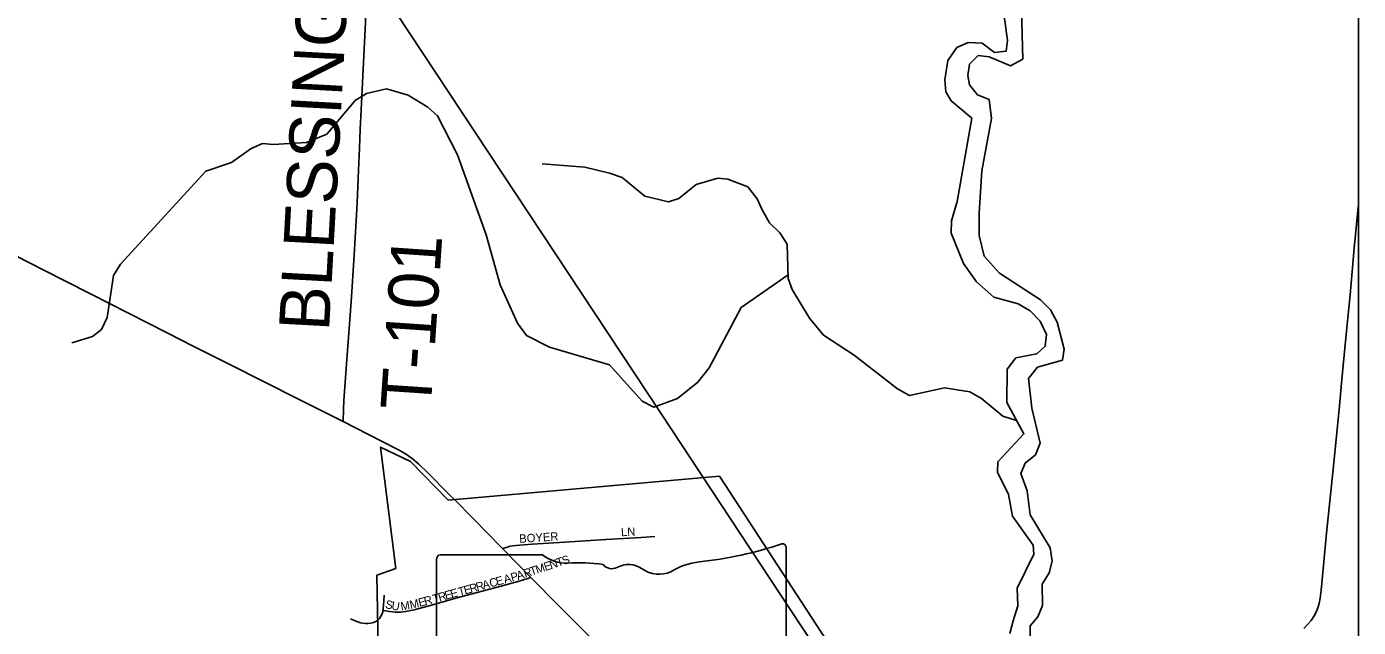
# Model space of a CAD drawing. Extents: x -49 to -8.2, y 9.4 to 23.5.
# Drawn here: x -40.243 to -39.49, y 18.85 to 19.19 of the extents above; entities that cross this region are included whole.
import ezdxf

# ---------------------------------------------------------------- set-up
doc = ezdxf.new("R2010")
doc.units = 0
for name, color, linetype in [('GM_X_Adjacent_County', 7, 'Continuous'), ('GM_X_City_Street', 7, 'Continuous'), ('GM_X_City_Street_Text', 7, 'Continuous'), ('GM_X_Corporation', 7, 'Continuous'), ('GM_X_Minor_River', 7, 'Continuous'), ('GM_X_Rail_Line', 7, 'Continuous'), ('GM_X_State_Route', 7, 'Continuous'), ('GM_X_State_Shield', 7, 'Continuous'), ('GM_X_Township_Road', 7, 'Continuous'), ('GM_X_Township_Road_Text', 7, 'Continuous')]:
    doc.layers.add(name, color=color, linetype=linetype)

msp = doc.modelspace()

# ---------------------------------------------------------------- linework, layer by layer
at = {"layer": 'GM_X_Adjacent_County'}
msp.add_lwpolyline([(-39.48954, 20.58796), (-39.48954, 17.08606), (-39.79885, 17.10416)], dxfattribs=at)
at = {"layer": 'GM_X_City_Street'}
for points in [[(-39.97381, 18.89488), (-39.97082, 18.89572), (-39.96933, 18.89614), (-39.9681, 18.89638), (-39.96627, 18.89659), (-39.95702, 18.89729), (-39.93848, 18.8984), (-39.91532, 18.89992), (-39.89524, 18.90118), (-39.88753, 18.90173)], [(-40.04134, 18.8599), (-40.03753, 18.85924), (-40.03606, 18.85906), (-40.03447, 18.85898), (-40.03133, 18.85892), (-40.02833, 18.85929), (-40.02372, 18.86022), (-40.01605, 18.8623), (-39.998, 18.86728), (-39.9752, 18.87347), (-39.96297, 18.87675), (-39.95767, 18.87857)], [(-40.04134, 18.8599), (-40.04117, 18.86082), (-40.04077, 18.86538), (-40.04065, 18.86844)], [(-40.05981, 18.85512), (-40.05699, 18.85391), (-40.05558, 18.85339), (-40.05413, 18.85295), (-40.05268, 18.85262), (-40.05122, 18.85247), (-40.04973, 18.85251), (-40.04825, 18.85269), (-40.0468, 18.85302), (-40.04544, 18.85353), (-40.04428, 18.85431), (-40.04332, 18.8554), (-40.0425, 18.85664), (-40.04185, 18.85795), (-40.04151, 18.85906), (-40.04134, 18.8599)]]:
    msp.add_lwpolyline(points, dxfattribs=at)
at = {"layer": 'GM_X_Corporation'}
msp.add_lwpolyline([(-39.7113, 18.72151), (-39.85087, 18.93577), (-40.00444, 18.92212), (-40.02576, 18.94403), (-40.04272, 18.95226), (-40.03415, 18.88366), (-40.04482, 18.87976), (-40.04155, 18.71218)], dxfattribs=at)
at = {"layer": 'GM_X_Minor_River'}
for points in [[(-39.67524, 18.83978), (-39.67518, 18.85116), (-39.6708, 18.85626), (-39.6683, 18.8627), (-39.66843, 18.87465), (-39.66442, 18.88108), (-39.66268, 18.88771), (-39.66397, 18.8953), (-39.67523, 18.91395), (-39.67686, 18.92743), (-39.68041, 18.93731), (-39.6781, 18.94318), (-39.67221, 18.94789), (-39.66953, 18.95451), (-39.67434, 18.97427), (-39.67615, 18.99097), (-39.67101, 18.99739), (-39.65698, 19.00131), (-39.656, 19.00756), (-39.65989, 19.02294), (-39.66364, 19.02979), (-39.66929, 19.03551), (-39.69249, 19.05061), (-39.70115, 19.06014), (-39.70412, 19.07192), (-39.70405, 19.08463), (-39.7026, 19.10833), (-39.69715, 19.13809), (-39.69842, 19.14872), (-39.70503, 19.15141), (-39.70954, 19.15712), (-39.71046, 19.16225), (-39.70948, 19.16869), (-39.70472, 19.1736), (-39.69848, 19.17281), (-39.68639, 19.16782), (-39.67937, 19.17158), (-39.68017, 19.19966)], [(-39.68984, 19.1961), (-39.68802, 19.18206), (-39.68881, 19.17599), (-39.69544, 19.17526), (-39.70241, 19.18061), (-39.71036, 19.18103), (-39.71662, 19.17821), (-39.72177, 19.17084), (-39.72353, 19.15985), (-39.723, 19.15301), (-39.71981, 19.14807), (-39.70812, 19.13814), (-39.71651, 19.09114), (-39.71979, 19.08015), (-39.71982, 19.07313)], [(-39.81217, 19.04952), (-39.83873, 19.03123), (-39.85689, 18.99699), (-39.86318, 18.98886), (-39.87477, 18.97962), (-39.88805, 18.97476), (-39.89465, 18.97821), (-39.91328, 18.99878), (-39.94712, 19.00863), (-39.96014, 19.01533), (-39.96522, 19.02237), (-39.97513, 19.04405), (-39.98294, 19.07216), (-39.99917, 19.11739), (-40.01041, 19.13945), (-40.01606, 19.14441), (-40.02701, 19.1511), (-40.03929, 19.15476), (-40.05066, 19.15216), (-40.05712, 19.14821), (-40.07312, 19.12913), (-40.08469, 19.12444), (-40.10343, 19.12321), (-40.10949, 19.12381), (-40.11594, 19.12099), (-40.12696, 19.11308), (-40.14156, 19.10822), (-40.18991, 19.05572), (-40.19373, 19.04929), (-40.19745, 19.02541), (-40.20052, 19.01878), (-40.20565, 19.01482), (-40.21741, 19.01109)], [(-39.68287, 18.96721), (-39.69065, 18.96979), (-39.70271, 18.97972), (-39.70931, 18.98355), (-39.72369, 18.9857), (-39.7434, 18.98144), (-39.75019, 18.98508), (-39.7747, 19.00417), (-39.79205, 19.01545), (-39.80014, 19.02516), (-39.8099, 19.04133), (-39.81214, 19.0476), (-39.81261, 19.06695), (-39.81674, 19.07342), (-39.82276, 19.07896), (-39.82689, 19.08638), (-39.8297, 19.09265), (-39.83496, 19.09931), (-39.8463, 19.10373), (-39.85197, 19.10433), (-39.8641, 19.1006), (-39.87399, 19.09268), (-39.87987, 19.09081), (-39.89329, 19.0941), (-39.90611, 19.1046), (-39.91328, 19.1071), (-39.92709, 19.11039), (-39.9513, 19.11241)], [(-39.71982, 19.07313), (-39.71291, 19.05603), (-39.70558, 19.04556), (-39.69578, 19.03697), (-39.68198, 19.0333), (-39.67519, 19.02928), (-39.66954, 19.02337), (-39.66599, 19.01596), (-39.66678, 19.00932), (-39.67153, 19.00498), (-39.68328, 19.00276), (-39.68823, 18.99634), (-39.68833, 18.97737), (-39.67877, 18.95968), (-39.69343, 18.94382), (-39.69365, 18.93813), (-39.68747, 18.92539), (-39.68526, 18.91324), (-39.67342, 18.89668), (-39.67307, 18.89174), (-39.68264, 18.87244), (-39.68212, 18.86239), (-39.68482, 18.85406), (-39.68675, 18.84686)]]:
    msp.add_lwpolyline(points, dxfattribs=at)
at = {"layer": 'GM_X_Rail_Line'}
msp.add_lwpolyline([(-39.62432, 18.5853), (-39.64583, 18.61097), (-39.65324, 18.62101), (-39.67003, 18.64579), (-39.7037, 18.69732), (-39.73465, 18.7448), (-39.81071, 18.86022), (-39.88413, 18.97135), (-40.04901, 19.22076)], dxfattribs=at)
at = {"layer": 'GM_X_State_Route'}
for points in [[(-39.52045, 18.84966), (-39.51828, 18.85184), (-39.51628, 18.85419), (-39.51454, 18.85673), (-39.51379, 18.85806), (-39.51259, 18.86086), (-39.51175, 18.8638), (-39.51112, 18.86681), (-39.51051, 18.87139), (-39.50731, 18.9054), (-39.504, 18.93785), (-39.50048, 18.97339), (-39.4988, 18.99039), (-39.4968, 19.01204), (-39.49423, 19.03831), (-39.49187, 19.06461), (-39.48966, 19.0878), (-39.48954, 19.08905)], [(-40.04214, 18.95566), (-40.0639, 18.96676), (-40.08719, 18.97838), (-40.11075, 18.99033), (-40.12603, 18.99798), (-40.13853, 19.00424), (-40.14828, 19.00906), (-40.16353, 19.01678), (-40.18567, 19.0281), (-40.20639, 19.03877), (-40.22164, 19.04647), (-40.24246, 19.05694), (-40.26727, 19.06986)], [(-40.00074, 18.92245), (-40.00384, 18.9255), (-40.01574, 18.93757), (-40.02132, 18.94284), (-40.02486, 18.94576), (-40.02862, 18.94837), (-40.03258, 18.95069), (-40.04214, 18.95566)], [(-39.78571, 18.6853), (-39.79173, 18.6926), (-39.81463, 18.71994), (-39.83438, 18.74385), (-39.8483, 18.7605), (-39.87303, 18.79035), (-39.88311, 18.80211), (-39.88936, 18.80898), (-39.9023, 18.82234), (-39.92507, 18.84561), (-39.94142, 18.86215), (-39.95767, 18.87857), (-39.97381, 18.89488), (-39.97414, 18.89522), (-39.99039, 18.91185), (-40.00074, 18.92245)]]:
    msp.add_lwpolyline(points, dxfattribs=at)
at = {"layer": 'GM_X_State_Shield'}
for p, q in [((-40.01102, 18.88876), (-40.01102, 18.73867)), ((-39.95116, 18.89135), (-40.00907, 18.89135)), ((-39.81327, 18.81655), (-39.81327, 18.89507))]:
    msp.add_line(p, q, dxfattribs=at)
for centre, radius, start, end in [((-39.88371, 19.09597), 0.20971, 275.84447, 288.90645), ((-39.81546, 18.89539), 0.0022, 351.86209, 97.738), ((-40.00875, 18.88908), 0.00229, 98.1301, 188.1301), ((-39.93737, 18.90877), 0.02222, 231.61951, 271.11188), ((-39.93, 18.80708), 0.07977, 80.48669, 94.98827), ((-39.91189, 18.88986), 0.00641, 219.79206, 297.10237), ((-39.90248, 18.87251), 0.01333, 54.46668, 119.14113), ((-39.88528, 18.89631), 0.01603, 233.85621, 294.82819), ((-39.85696, 18.84551), 0.04219, 97.34618, 120.76885)]:
    msp.add_arc(centre, radius, start, end, dxfattribs=at)
at = {"layer": 'GM_X_Township_Road'}
msp.add_lwpolyline([(-40.0639, 18.96676), (-40.06368, 18.9739), (-40.06348, 18.97855), (-40.06186, 19.0018), (-40.05939, 19.03433), (-40.05759, 19.06066), (-40.05604, 19.09013), (-40.05519, 19.10876), (-40.05465, 19.12117), (-40.0542, 19.13203), (-40.05374, 19.14289), (-40.05128, 19.19253), (-40.05049, 19.21116), (-40.05038, 19.21737), (-40.05024, 19.21891), (-40.05018, 19.22029), (-40.05009, 19.22147)], dxfattribs=at)

# ---------------------------------------------------------------- texts
at = {"layer": 'GM_X_City_Street_Text'}
for s, height, rotation, p in [('BOYER', 0.004735, 3.65478, (-39.9641, 18.89804)), ('LN', 0.004735, 3.01158, (-39.90659, 18.90179)), ('N', 0.00473, 18.44132, (-39.9463, 18.88317)), ('T', 0.00473, 18.45788, (-39.94234, 18.88449)), ('S', 0.00473, 18.42631, (-39.93918, 18.88554)), ('P', 0.00473, 15.3447, (-39.96839, 18.87613)), ('A', 0.00473, 16.86767, (-39.96505, 18.87705)), ('R', 0.00473, 18.36281, (-39.96093, 18.8783)), ('T', 0.00473, 18.44274, (-39.95737, 18.87948)), ('M', 0.00473, 18.45487, (-39.9542, 18.88054)), ('E', 0.00473, 18.42631, (-39.94946, 18.88212)), ('T', 0.00473, 15.31501, (-39.99814, 18.86798)), ('E', 0.00473, 15.3447, (-39.99492, 18.86886)), ('R', 0.00473, 15.3382, (-39.99171, 18.86974)), ('R', 0.00473, 15.31477, (-39.98809, 18.87073)), ('A', 0.00473, 15.32963, (-39.98447, 18.87172)), ('C', 0.00473, 15.33237, (-39.98046, 18.87282)), ('E', 0.00473, 15.31501, (-39.97684, 18.87381)), ('A', 0.00473, 15.3088, (-39.97242, 18.87503)), ('S', 0.00473, 345.58603, (-40.04045, 18.86134)), ('M', 0.00473, 13.47537, (-40.02568, 18.86061)), ('E', 0.00473, 15.19247, (-40.02067, 18.86181)), ('R', 0.00473, 15.31797, (-40.01744, 18.86269)), ('T', 0.00473, 15.3447, (-40.01261, 18.86401)), ('R', 0.00473, 15.31477, (-40.0094, 18.86489)), ('E', 0.00473, 15.3447, (-40.00578, 18.86588)), ('E', 0.00473, 15.31501, (-40.00256, 18.86676)), ('U', 0.00473, 350.98994, (-40.03675, 18.86041)), ('M', 0.00473, 8.85851, (-40.03103, 18.85976))]:
    msp.add_text(s, height=height, rotation=rotation, dxfattribs=at).set_placement(p)
at = {"layer": 'GM_X_Township_Road_Text'}
for s, rotation, p in [('BLESSING', 86.86671, (-40.07187, 19.01737)), ('T-101', 86.14967, (-40.01444, 18.97242))]:
    msp.add_text(s, height=0.028409, rotation=rotation, dxfattribs=at).set_placement(p)

doc.saveas('drawing.dxf')
